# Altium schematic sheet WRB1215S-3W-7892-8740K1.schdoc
size 277 x 190 mm; Device: default297x210; Symbol: default297x210; Name: default297x210; Date: 2025.07.09; Rev: V1.1; Size: "A4"; Id: /; File: WRB1215S-3W-7892-8740K1; Sheet: /; @Page No: 1; @Page Count: 1; @Schematic Name: WRB1215S-3W-7892-8740K1; @Project Name: 无光耦反激隔离电源WRB1215S-3W-7892-8740K1; @Board Name: WRB1215S-3W-7892-8740K1; @Update Date: 2025-07-09; @Create Time: 14:48:33; @Update Time: 13:57:20; @Page Name: WRB1215S-3W-7892-8740K1; @Create Date: 2025-07-03
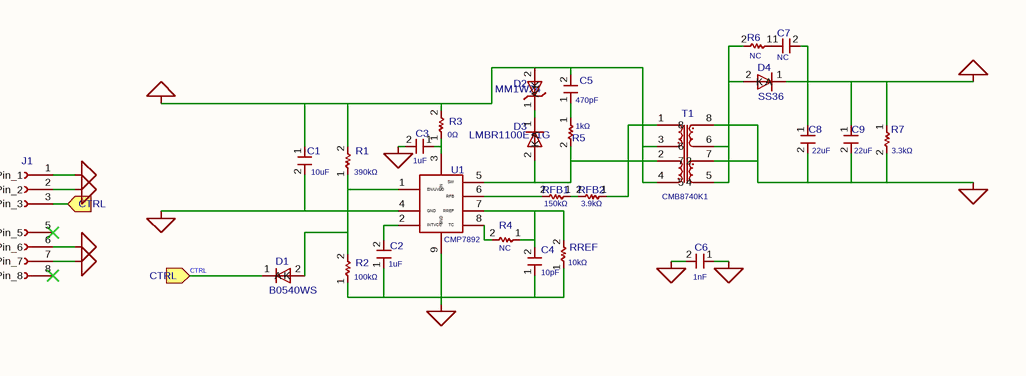
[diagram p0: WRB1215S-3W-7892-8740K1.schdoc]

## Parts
C1  10uF  [C0805]
C2  1uF  [C0603]
C3  1uF  [C0603]
C4  10pF  [C0603]
C5  470pF  [C0603]
C6  1nF  [C1206]
C7  NC  [C0603]
C8  22uF  [C0805]
C9  22uF  [C0805]
D1  B0540WS  [SOD-323_L1.8-W1.3-LS2.5-RD]
D2  MM1W24  [SOD-123_L2.8-W1.8-LS3.9-FD]
D3  LMBR1100ET1G  [SOD-323HE_L1.9-W1.3-LS2.5-RD]
D4  SS36  [SMA_L4.3-W2.6-LS5.2-RD]
J1  conn_01x08  [coileasy:PinHeader_01x07_1_P2.54mm_Vertical]  (value not drawn)
R1  390kΩ  [R0603]
R2  100kΩ  [R0603]
R3  0Ω  [R0603]
R4  NC  [R0603]
R5  1kΩ  [R0603]
R6  NC  [R0603]
R7  3.3kΩ  [R0805]
RFB1  150kΩ  [R0603]
RFB2  3.9kΩ  [R0603]
RREF  10kΩ  [R0603]
T1  CMB8740K1  [coileasy:SMD-8P, 11.55x9.6, ER9.5 4+4]
U1  CMP7892  [coileasy:ESOP-8]

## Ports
CTRL (in)

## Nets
GND1: C1.2 C2.1 C3.2 C4.1 C6.2 J1.1(Pin_1) R2.1 RREF.1 U1.4(GND) U1.9(GND)
GND2: C6.1 C8.2 C9.2 J1.7(Pin_7) R7.2 T1.7 T1.8
VIN: C1.1 C5.2 D2.2(A) J1.2(Pin_2) R1.2 R3.2 T1.3 T1.4
VO: C7.2 C8.1 C9.1 D4.1(K) J1.6(Pin_6) R7.1
CTRL: D1.1(K) J1.3(Pin_3) ; port CTRL
NetC2_2: C2.2 U1.2(INTVCC)
NetC3_1: C3.1 R3.1 U1.3(VIN)
NetC4_2: C4.2 R4.1 RREF.2 U1.7(RREF)
NetC5_1: C5.1 R5.1
NetC7_1: C7.1 R6.1
NetD1_2: D1.2(A) R1.1 R2.2 U1.1(EN/UVLO)
NetD2_1: D2.1(K) D3.1(K)
NetD3_2: D3.2(A) R5.2 RFB2.1 T1.1 T1.2 U1.5(SW)
NetD4_2: D4.2(A) R6.2 T1.5 T1.6
NetR4_2: R4.2 U1.8(TC)
NetRFB1_1: RFB1.1 RFB2.2
NetRFB1_2: RFB1.2 U1.6(RFB)

Not connected (* = marked no-connect by the designer): J1 5(Pin_5)* 8(Pin_8)*

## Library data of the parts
C1 = CGA0805X5R106K350MT: 容值:10uF;精度:±10%;额定电压:35V;温度系数:X5R;; Manufacturer: HRE(芯声); Symbol: MY_C; AddInBom: yes; ModelId: 1ba041120af144c991958decab20d241; ModelName: C0805_L2.0-W1.3-H1.3; ModelTransform: 78.74,51.181,0,0,0,0,0,0.0005,0; Tolerance: ±10%; Voltage Rating: 35V; Temperature Coefficient: X5R
C2 C3 = 0603X105K500NT: 容值:1uF;精度:±10%;额定电压:50V;温度系数:X5R;; Manufacturer: FH(风华); Symbol: MY_C; AddInBom: yes; ModelId: ac125912035d415993ca9572d50418b1; ModelName: C0603_L1.6-W0.8-H0.8; ModelTransform: 62.992,31.496,0,0,0,0,0,0,0; Tolerance: ±10%; Voltage Rating: 50V; Temperature Coefficient: X5R
C4 = CC0603JRNPO9BN100: 容值:10pF;精度:±5%;额定电压:50V;材质(温度系数):NP0;; Manufacturer: YAGEO(国巨); Symbol: C; AddInBom: yes; ModelId: ac125912035d415993ca9572d50418b1; ModelName: C0603_L1.6-W0.8-H0.8; ModelTransform: 62.992,31.496,0,0,0,0,0,0,0; Tolerance: ±5%; Voltage Rated: 50V; Temperature Coefficient: NP0
C5 = CC0603KRX7R9BB471: 容值:470pF;精度:±10%;额定电压:50V;材质(温度系数):X7R;; Manufacturer: YAGEO(国巨); Symbol: C; AddInBom: yes; ModelId: ac125912035d415993ca9572d50418b1; ModelName: C0603_L1.6-W0.8-H0.8; ModelTransform: 62.992,31.496,0,0,0,0,0,0,0; Tolerance: ±10%; Voltage Rated: 50V; Temperature Coefficient: X7R
C6 = CC1206KKX7RDBB102: 容值:1nF;精度:±10%;额定电压:2kV;材质(温度系数):X7R;; Manufacturer: YAGEO(国巨); Symbol: MY_C; AddInBom: yes; ModelId: e4be705b945545a48e666415e3682bd8; ModelName: C1206_L3.2-W1.6-H1.3; ModelTransform: 125.984,62.992,0,0,0,0,0,0,0; Tolerance: ±10%; Voltage Rated: 2kV; Temperature Coefficient: X7R
C7 = C: AddInBom: yes; Tolerance: ±5%
C8 C9 = 0805X226M250NT: 容值:22uF;精度:±20%;额定电压:25V;温度系数:X5R;; Manufacturer: FH(风华); Symbol: MY_C; AddInBom: yes; ModelId: 1ba041120af144c991958decab20d241; ModelName: C0805_L2.0-W1.3-H1.3; ModelTransform: 78.74,51.181,0,0,0,0,0,0.0005,0; Tolerance: ±20%; Voltage Rating: 25V; Temperature Coefficient: X5R
D1 = B0540WS_C475613: 二极管配置:独立式;正向压降(Vf):600mV@200mA;直流反向耐压(Vr):40V;平均整流电流(Io):350mA;; Manufacturer: SHIKUES(时科); Symbol: Coileasy library_D; AddInBom: yes; ModelId: 7459fe65e23146c0a8d836e46a0add72; ModelTransform: 104.3305,51.181,0,0,0,0,0,0,0; Diode Configuration: 独立式; Reverse Voltage (Vr): 40V; Average Rectified Current (Io): 350mA; Reverse Leakage Current (Ir): 5uA@30V
D2 = MM1W24_C22395531: 二极管配置:独立式;稳压值(标称值):24V;稳压值(范围):22.8V~26V;功率(Pd):1W;; Manufacturer: 宏迦橙; Symbol: My library_D_Zener; AddInBom: yes; ModelId: 0d1aa9d5d9b94beba87ba53253e19c9b; ModelTransform: 145.669,70.866,0,180,0,0,0,0,0; Diode Configuration: 独立式; Zener Voltage (Nom): 24V; Reverse Leakage Current (Ir): 5uA@18V; Power Dissipation: 1W; Zener Impedance (Zzt): 25Ω
D3 = LMBR1100ET1G_C20622202: 直流反向耐压(Vr):100V;整流电流:1A;; Manufacturer: DOWO(东沃); Symbol: My library_DSS210; AddInBom: yes; ModelId: 6e7329c6fa044decaae410a44b76a6a6; ModelName: SOD-323HE_L2.0-W1.4-LS2.5-RD; ModelTransform: 98.425,51.181,0,0,0,0,-7.917,0,0; Voltage - DC Reverse(Vr): 100V; Current - Rectified: 1A
D4 = SS36_C16015: 二极管配置:独立式;正向压降(Vf):700mV@3A;直流反向耐压(Vr):60V;整流电流:3A;; Manufacturer: MDD(辰达半导体); Symbol: My library_DSS210; AddInBom: yes; ModelId: e3551acb3c5a4975a5e9d36087fe1fa2; ModelTransform: 185.039,102.362,0,0,0,0,0,0,0; Diode Configuration: 独立式; Reverse Voltage (Vr): 60V; Rectified Current: 3A; Reverse Leakage Current (Ir): 500uA@60V
J1 = conn_01x08: Symbol: Coileasy_Conn_01x07_1; AddInBom: yes
R1 = RC0603FR-07390KL: 电阻类型:厚膜电阻;阻值:390kΩ;精度:±1%;功率:100mW;最大工作电压:75V;温度系数:±100ppm/℃;; Manufacturer: YAGEO(国巨); Symbol: R; AddInBom: yes; ModelId: fc143cca1e79419f9cd78b61e9279f08; ModelTransform: 31.8897,63.7794,0,90,0,0,0,0,0; Tolerance: ±1%; Power(Watts): 100mW; Overload Voltage (Max): 75V
R2 = RC0603FR-07100KL: 电阻类型:厚膜电阻;阻值:100kΩ;精度:±1%;功率:100mW;最大工作电压:75V;温度系数:±100ppm/℃;; Manufacturer: YAGEO(国巨); Symbol: R; AddInBom: yes; ModelId: fc143cca1e79419f9cd78b61e9279f08; ModelTransform: 31.8897,63.7794,0,90,0,0,0,0,0; Tolerance: ±1%; Power(Watts): 100mW; Overload Voltage (Max): 75V
R3 = RC0603FR-070RL: 电阻类型:厚膜电阻;阻值:0Ω;精度:±1%;功率:100mW;工作电压:75V;温度系数:-;; Manufacturer: YAGEO(国巨); Symbol: R; AddInBom: yes; ModelId: fc143cca1e79419f9cd78b61e9279f08; ModelTransform: 31.8897,63.7794,0,90,0,0,0,0,0; Tolerance: ±1%; Power(Watts): 100mW; Voltage-Supply(Max): 75V
R4 R6 = R: 电阻类型:厚膜电阻;阻值:10kΩ;精度:±1%;功率:100mW;最大工作电压:75V;温度系数:±100ppm/℃;; AddInBom: yes; Tolerance: ±1%; Power(Watts): 100mW; Overload Voltage (Max): 75V
R5 = RC0603FR-071KL: 电阻类型:厚膜电阻;阻值:1kΩ;精度:±1%;功率:100mW;工作电压:75V;温度系数:±100ppm/℃;; Manufacturer: YAGEO(国巨); Symbol: R; AddInBom: yes; ModelId: fc143cca1e79419f9cd78b61e9279f08; ModelTransform: 31.8897,63.7794,0,90,0,0,0,0,0; Tolerance: ±1%; Power(Watts): 100mW; Voltage-Supply(Max): 75V
R7 = RC0805FR-073K3L: 电阻类型:厚膜电阻;阻值:3.3kΩ;精度:±1%;功率:125mW;最大工作电压:150V;温度系数:±100ppm/℃;; Manufacturer: YAGEO(国巨); Symbol: R; AddInBom: yes; ModelId: 37a81e68749a4138bd2dfa6897b24b85; ModelName: R0805_L2.0-W1.3-H0.6; ModelTransform: 78.74,51.181,0,0,0,0,0,-0.0005,0; Tolerance: ±1%; Power(Watts): 125mW; Overload Voltage (Max): 150V
RFB1 = RC0603FR-07150KL: 电阻类型:厚膜电阻;阻值:150kΩ;精度:±1%;功率:100mW;最大工作电压:75V;温度系数:±100ppm/℃;; Manufacturer: YAGEO(国巨); Symbol: R; AddInBom: yes; ModelId: fc143cca1e79419f9cd78b61e9279f08; ModelTransform: 31.8897,63.7794,0,90,0,0,0,0,0; Tolerance: ±1%; Power(Watts): 100mW; Overload Voltage (Max): 75V
RFB2 = RC0603FR-073K9L: 电阻类型:厚膜电阻;阻值:3.9kΩ;精度:±1%;功率:100mW;最大工作电压:75V;温度系数:±100ppm/℃;; Manufacturer: YAGEO(国巨); Symbol: R; AddInBom: yes; ModelId: fc143cca1e79419f9cd78b61e9279f08; ModelTransform: 31.8897,63.7794,0,90,0,0,0,0,0; Tolerance: ±1%; Power(Watts): 100mW; Overload Voltage (Max): 75V
RREF = RC0603FR-0710KL: 电阻类型:厚膜电阻;阻值:10kΩ;精度:±1%;功率:100mW;最大工作电压:75V;温度系数:±100ppm/℃;; Manufacturer: YAGEO(国巨); Symbol: R; AddInBom: yes; ModelId: fc143cca1e79419f9cd78b61e9279f08; ModelTransform: 31.8897,63.7794,0,90,0,0,0,0,0; Tolerance: ±1%; Power(Watts): 100mW; Overload Voltage (Max): 75V
T1 = CMB8740K1: AddInBom: yes
U1 = CMP7892: AddInBom: yes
